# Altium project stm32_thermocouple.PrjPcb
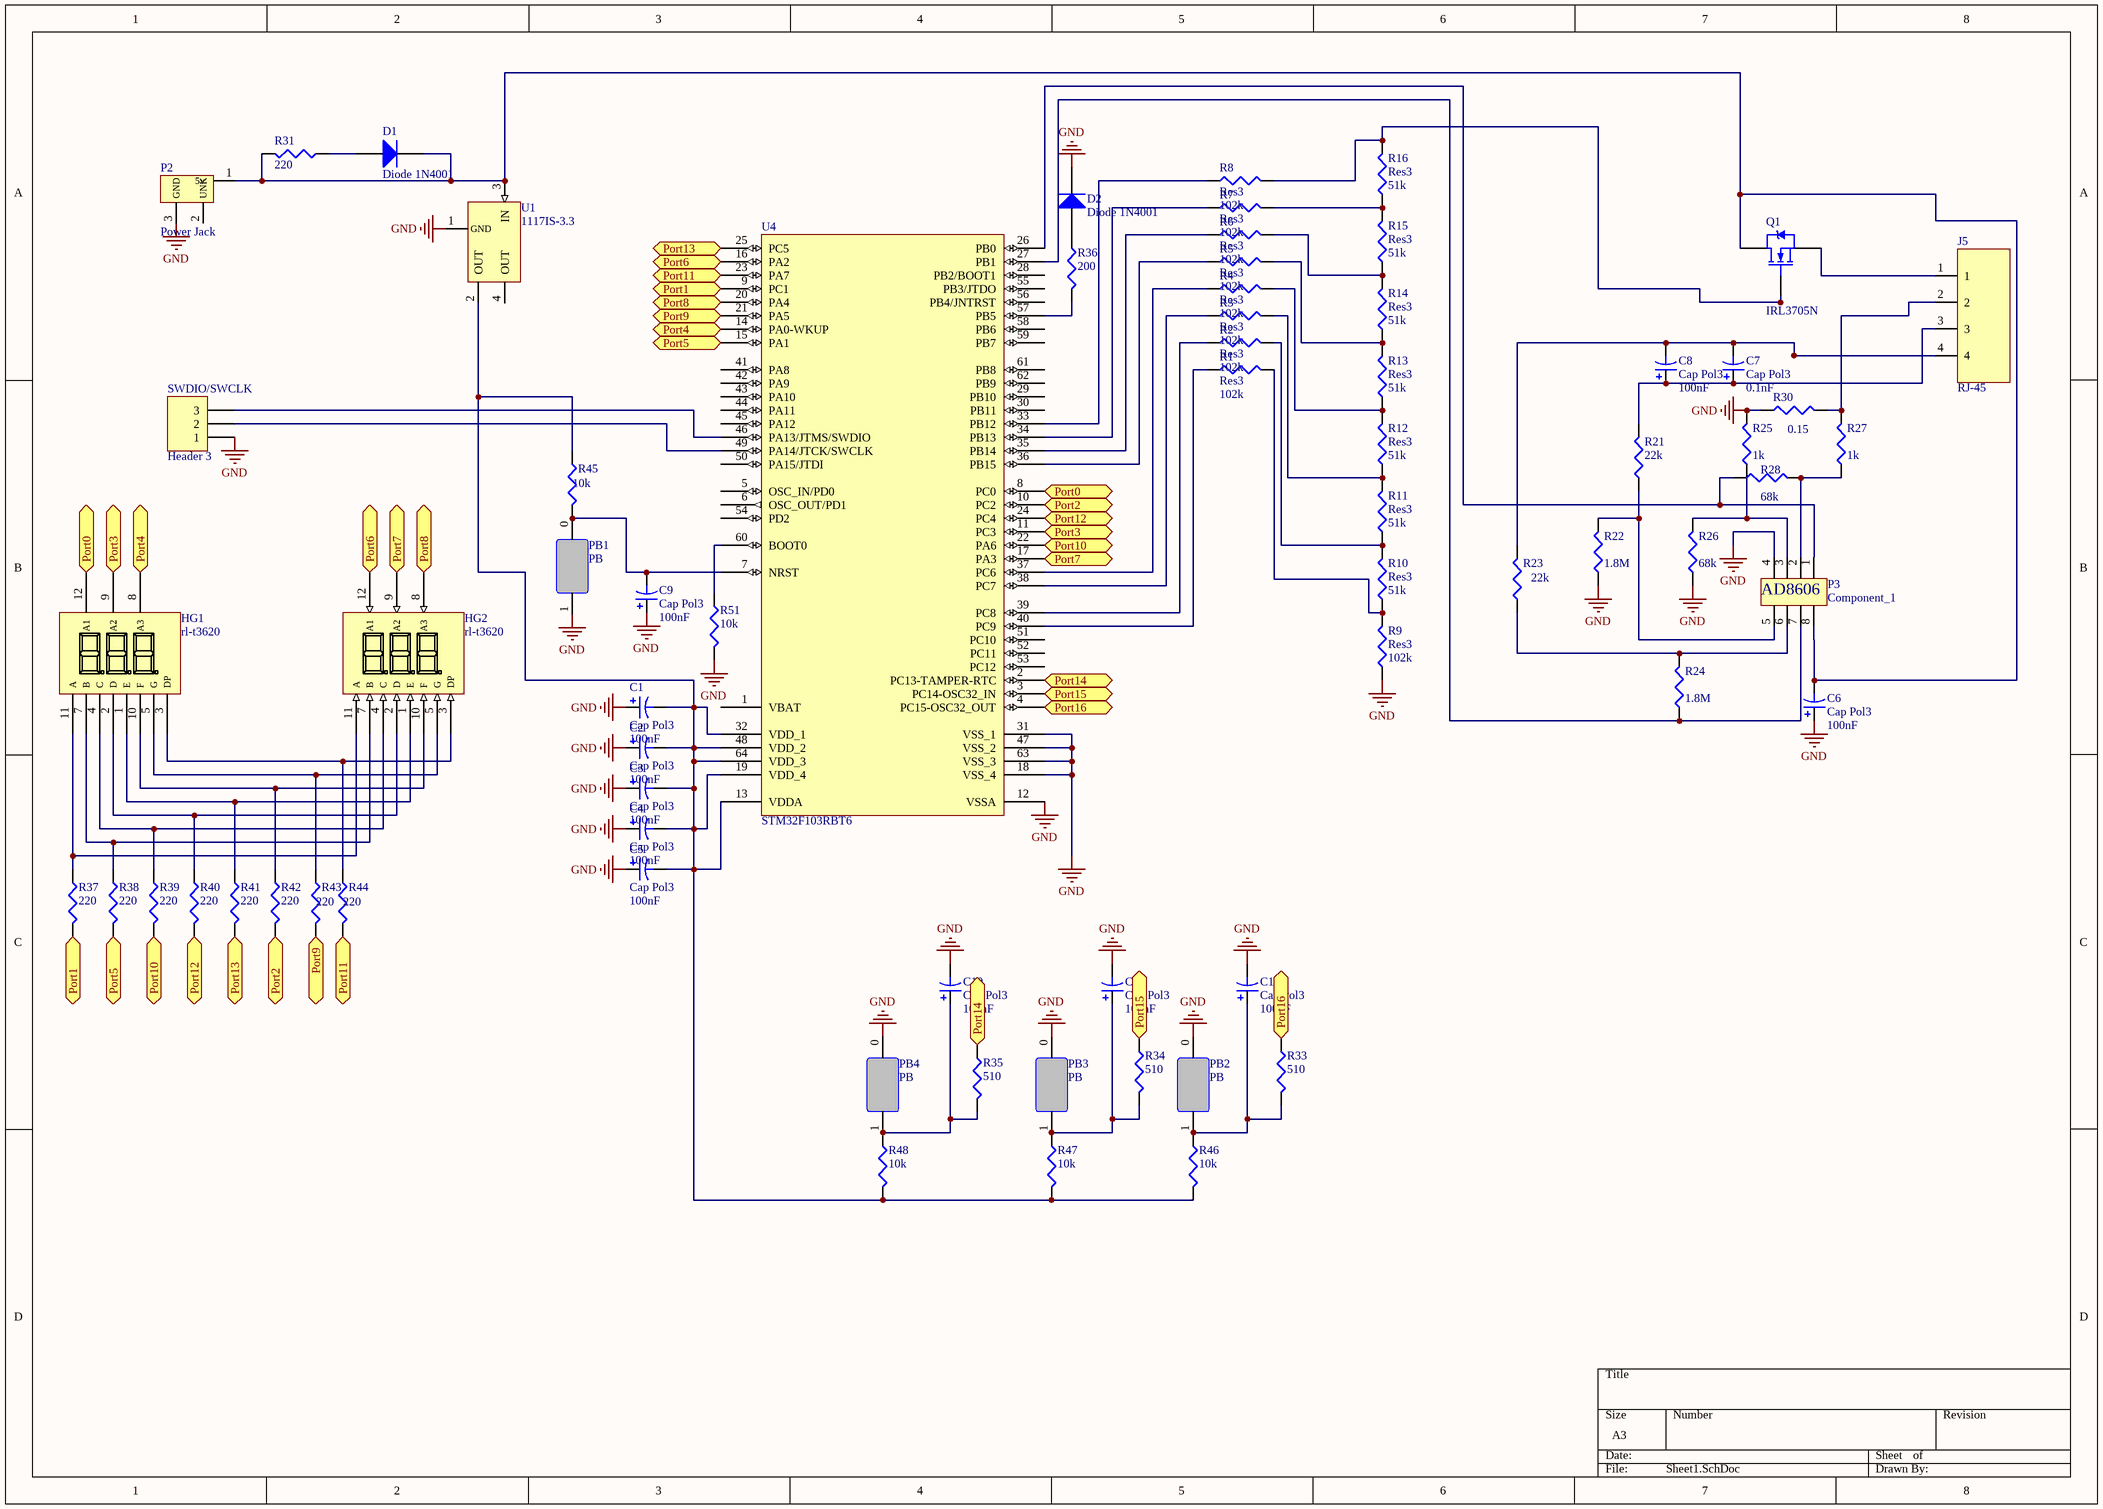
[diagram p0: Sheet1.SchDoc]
1 sheet, 70 parts. Net scope: flat (ports and power ports of the same name join across sheets).
Board file: PCB1.PcbDoc

## Sheet Sheet1.SchDoc
size A3

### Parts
C1  Cap Pol3  value 100nF  [C0805]
C2  Cap Pol3  value 100nF  [C0805]
C3  Cap Pol3  value 100nF  [C0805]
C4  Cap Pol3  value 100nF  [C0805]
C5  Cap Pol3  value 100nF  [C0805]
C6  Cap Pol3  value 100nF  [C0805]
C7  Cap Pol3  value 0.1nF  [C0805]
C8  Cap Pol3  value 100nF  [C0805]
C9  Cap Pol3  value 100nF  [C0805]
C10  Cap Pol3  value 100nF  [C0805]
C11  Cap Pol3  value 100nF  [C0805]
C12  Cap Pol3  value 100nF  [C0805]
D1  Diode 1N4001  [DO-41]
D2  Diode 1N4001  [DO-41]
HG1  rl-t3620  [PCBComponent_1]
HG2  rl-t3620  [PCBComponent_1]
J5  RJ-45  [rj_45]
P2  Power Jack  [PCBComponent_1]
P3  Component_1  [MSOP-8]
PB1  PB  [button1]
PB2  PB  [button1]
PB3  PB  [button1]
PB4  PB  [button1]
Q1  IRL3705N  [TO-220AB]
R1  Res3  value 102k  [J1-0603]
R2  Res3  value 102k  [J1-0603]
R3  Res3  value 102k  [J1-0603]
R4  Res3  value 102k  [J1-0603]
R5  Res3  value 102k  [J1-0603]
R6  Res3  value 102k  [J1-0603]
R7  Res3  value 102k  [J1-0603]
R8  Res3  value 102k  [J1-0603]
R9  Res3  value 102k  [J1-0603]
R10  Res3  value 51k  [J1-0603]
R11  Res3  value 51k  [J1-0603]
R12  Res3  value 51k  [J1-0603]
R13  Res3  value 51k  [J1-0603]
R14  Res3  value 51k  [J1-0603]
R15  Res3  value 51k  [J1-0603]
R16  Res3  value 51k  [J1-0603]
R21  value 22k  [J1-0603]  (hidden comment: Res3)
R22  value 1.8M  [J1-0603]  (hidden comment: Res3)
R23  value 22k  [J1-0603]  (hidden comment: Res3)
R24  value 1.8M  [J1-0603]  (hidden comment: Res3)
R25  value 1k  [J1-0603]  (hidden comment: Res3)
R26  value 68k  [J1-0603]  (hidden comment: Res3)
R27  value 1k  [J1-0603]  (hidden comment: Res3)
R28  value 68k  [J1-0603]  (hidden comment: Res3)
R30  value 0.15  [J1-0603]  (hidden comment: Res3)
R31  value 220  [J1-0603]  (hidden comment: Res3)
R33  value 510  [J1-0603]  (hidden comment: Res3)
R34  value 510  [J1-0603]  (hidden comment: Res3)
R35  value 510  [J1-0603]  (hidden comment: Res3)
R36  value 200  [J1-0603]  (hidden comment: Res3)
R37  value 220  [J1-0603]  (hidden comment: Res3)
R38  value 220  [J1-0603]  (hidden comment: Res3)
R39  value 220  [J1-0603]  (hidden comment: Res3)
R40  value 220  [J1-0603]  (hidden comment: Res3)
R41  value 220  [J1-0603]  (hidden comment: Res3)
R42  value 220  [J1-0603]  (hidden comment: Res3)
R43  value 220  [J1-0603]  (hidden comment: Res3)
R44  value 220  [J1-0603]  (hidden comment: Res3)
R45  value 10k  [J1-0603]  (hidden comment: Res3)
R46  value 10k  [J1-0603]  (hidden comment: Res3)
R47  value 10k  [J1-0603]  (hidden comment: Res3)
R48  value 10k  [J1-0603]  (hidden comment: Res3)
R51  value 10k  [J1-0603]  (hidden comment: Res3)
SWDIO/SWCLK  Header 3  [HDR1X3]
U1  1117IS-3.3  [SOT223_N]
U4  STM32F103RBT6  [LQFP64_N]

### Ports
Port0, Port1, Port2, Port3, Port4, Port5, Port6, Port7, Port8, Port9, Port10, Port11, Port12, Port13, Port14, Port15, Port16

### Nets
GND: C1.1 C2.1 C3.1 C4.1 C5.1 C6.1 C9.1 C10.2 C11.2 C12.2 D2.2(K) P2.3(GND) P3.4 PB1.1 PB2.0 PB3.0 PB4.0 R9.1 R22.1 R25.2 R26.1 R30.1 R51.2 SWDIO/SWCLK.1 U1.1(GND) U4.12(VSSA) U4.18(VSS_4) U4.31(VSS_1) U4.47(VSS_2) U4.63(VSS_3)
NetC1_2: C1.2 C2.2 C3.2 C4.2 C5.2 R45.1 R46.2 R47.2 R48.2 U1.2(OUT) U4.13(VDDA) U4.19(VDD_4) U4.32(VDD_1) U4.48(VDD_2) U4.64(VDD_3)
NetC6_2: C6.2 D1.2(K) P2.1(5v) P3.8 Q1.2(D) R31.2 U1.3(IN)
NetC7_1: C7.1 C8.1 J5.3 R21.2
NetC7_2: C7.2 C8.2 J5.4 R23.2
NetC9_2: C9.2 PB1.0 R45.2 U4.7(NRST)
NetC10_1: C10.1 PB4.1 R35.2 R48.1
NetC11_1: C11.1 PB3.1 R34.2 R47.1
NetC12_1: C12.1 PB2.1 R33.2 R46.1
NetD1_1: D1.1(A) R31.1
NetD2_1: D2.1(A) R36.1
NetHG1_1: HG1.1(E) HG2.1(E) R41.1
NetHG1_2: HG1.2(D) HG2.2(D) R40.1
NetHG1_3: HG1.3(DP) HG2.3(DP) R44.1
NetHG1_4: HG1.4(C) HG2.4(C) R39.1
NetHG1_5: HG1.5(G) HG2.5(G) R43.1
NetHG1_7: HG1.7(B) HG2.7(B) R38.1
NetHG1_8: HG1.8(A3) U4.14(PA0-WKUP) ; port Port4
NetHG1_9: HG1.9(A2) U4.11(PC3) ; port Port3
NetHG1_10: HG1.10(F) HG2.10(F) R42.1
NetHG1_11: HG1.11(A) HG2.11(A) R37.1
NetHG1_12: HG1.12(A1) U4.8(PC0) ; port Port0
NetHG2_8: HG2.8(A3) U4.20(PA4) ; port Port8
NetHG2_9: HG2.9(A2) U4.17(PA3) ; port Port7
NetHG2_12: HG2.12(A1) U4.16(PA2) ; port Port6
NetJ5_1: J5.1 Q1.3(S)
NetJ5_2: J5.2 R27.2 R30.2
NetP3_1: P3.1 R28.1 U4.26(PB0)
NetP3_2: P3.2 R27.1 R28.2
NetP3_3: P3.3 R25.1 R26.2
NetP3_5: P3.5 R21.1 R22.2
NetP3_6: P3.6 R23.1 R24.2
NetP3_7: P3.7 R24.1 U4.27(PB1)
NetQ1_1: Q1.1(G) R8.2 R16.2
NetR1_1: R1.1 U4.40(PC9)
NetR1_2: R1.2 R9.2 R10.1
NetR2_1: R2.1 U4.39(PC8)
NetR2_2: R2.2 R10.2 R11.1
NetR3_1: R3.1 U4.38(PC7)
NetR3_2: R3.2 R11.2 R12.1
NetR4_1: R4.1 U4.37(PC6)
NetR4_2: R4.2 R12.2 R13.1
NetR5_1: R5.1 U4.36(PB15)
NetR5_2: R5.2 R13.2 R14.1
NetR6_1: R6.1 U4.35(PB14)
NetR6_2: R6.2 R14.2 R15.1
NetR7_1: R7.1 U4.34(PB13)
NetR7_2: R7.2 R15.2 R16.1
NetR8_1: R8.1 U4.33(PB12)
NetR33_1: R33.1 U4.4(PC15-OSC32_OUT) ; port Port16
NetR34_1: R34.1 U4.3(PC14-OSC32_IN) ; port Port15
NetR35_1: R35.1 U4.2(PC13-TAMPER-RTC) ; port Port14
NetR36_2: R36.2 U4.57(PB5)
NetR37_2: R37.2 U4.9(PC1) ; port Port1
NetR38_2: R38.2 U4.15(PA1) ; port Port5
NetR39_2: R39.2 U4.22(PA6) ; port Port10
NetR40_2: R40.2 U4.24(PC4) ; port Port12
NetR41_2: R41.2 U4.25(PC5) ; port Port13
NetR42_2: R42.2 U4.10(PC2) ; port Port2
NetR43_2: R43.2 U4.21(PA5) ; port Port9
NetR44_2: R44.2 U4.23(PA7) ; port Port11
NetR51_1: R51.1 U4.60(BOOT0)
NetSWDIO/SWCLK_2: SWDIO/SWCLK.2 U4.49(PA14/JTCK/SWCLK)
NetSWDIO/SWCLK_3: SWDIO/SWCLK.3 U4.46(PA13/JTMS/SWDIO)

Not connected (* = marked no-connect by the designer): P2 2(UNK); U1 4(OUT); U4 1(VBAT) 5(OSC_IN/PD0) 6(OSC_OUT/PD1) 28(PB2/BOOT1) 29(PB10) 30(PB11) 41(PA8) 42(PA9) 43(PA10) 44(PA11) 45(PA12) 50(PA15/JTDI) 51(PC10) 52(PC11) 53(PC12) 54(PD2) 55(PB3/JTDO) 56(PB4/JNTRST) 58(PB6) 59(PB7) 61(PB8) 62(PB9)

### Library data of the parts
C1-C12 = Cap Pol3: Polarized Capacitor (Surface Mount)
D1 D2 = Diode 1N4001: 1 Amp General Purpose Rectifier
P2 = Component_1
PB1-PB4 = button1
Q1 = IRL3705N: HEXFET Power MOSFET; Note: Pin 2 is electrically connected to pin 4 (Drain).
R1-R16 R21-R28 R30 R31 R33-R48 R51 = Res3: Resistor
SWDIO/SWCLK = Header 3: Header, 3-Pin
U4 = STM32F103RBT6: STM32 ARM-based 32-bit MCU with 128 Kbytes Flash, 64-pin LQFP, Industrial Temperature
